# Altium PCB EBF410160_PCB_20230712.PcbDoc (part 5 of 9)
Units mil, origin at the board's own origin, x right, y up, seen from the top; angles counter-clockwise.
Board outline 5393.69 x 3858.26 mil, 6 copper layers (TOP, GND02, ART03, POW04, GND05, BOTTOM), stack 47.2 mil thick; 572 components, 434 nets, 2057 pads, 1177 vias.
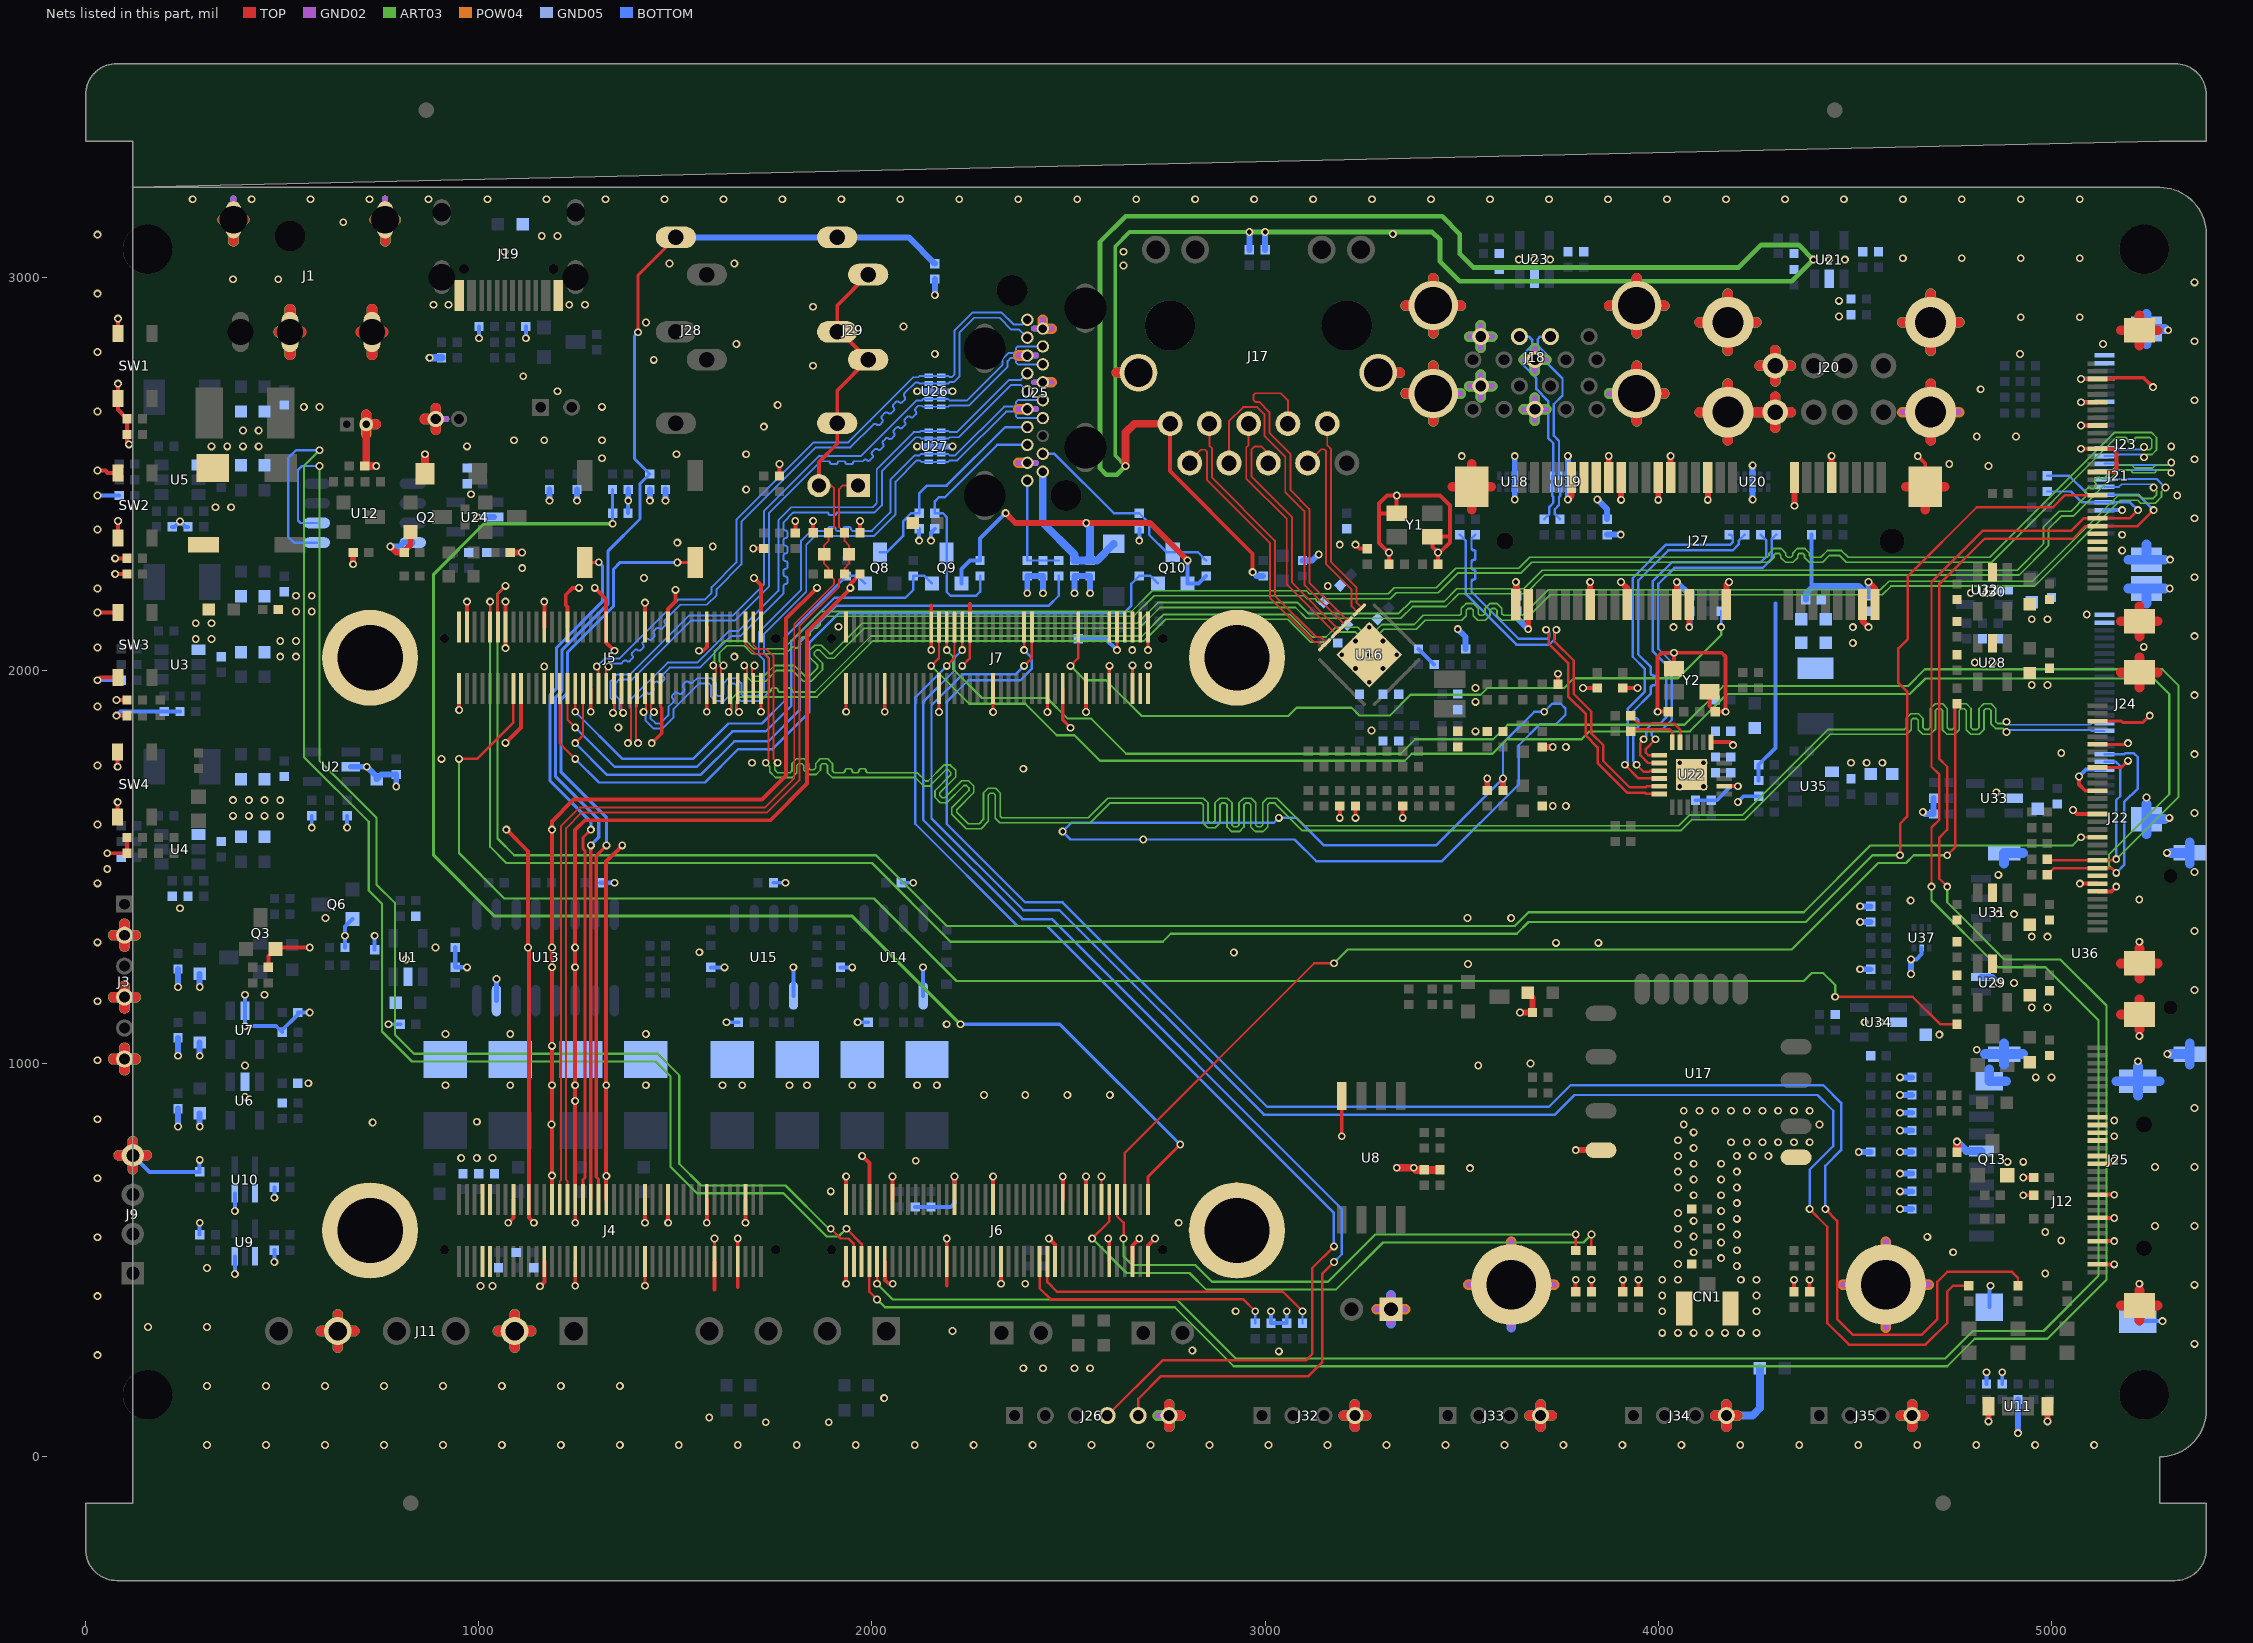
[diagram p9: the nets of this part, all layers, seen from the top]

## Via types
v1: diameter 20, hole 12, TOP to BOTTOM, 1177 vias

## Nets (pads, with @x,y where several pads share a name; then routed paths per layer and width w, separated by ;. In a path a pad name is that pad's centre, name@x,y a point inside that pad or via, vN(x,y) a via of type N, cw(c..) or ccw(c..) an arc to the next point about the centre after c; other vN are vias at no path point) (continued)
GND: (continued)
  other v1: 308.67,30 458.67,30 608.67,30 758.67,30 908.67,30 1058.67,30 1208.67,30 1358.67,30 1508.67,30 1658.67,30 1808.67,30 1958.67,30 2108.67,30 2258.67,30 2408.67,30 2558.67,30 2708.67,30 2858.67,30 3008.67,30 3158.67,30 3308.67,30 3458.67,30 3608.67,30 3758.67,30 3908.67,30 4058.67,30 4208.67,30 4358.67,30 4508.67,30 4658.67,30 4808.67,30 4958.67,30 5108.67,30 1730,87.75 1890,87.75 1586,99.75 2031,149 308.67,180 458.67,180 608.67,180 758.67,180 908.67,180 1058.67,180 1208.67,180 1358.67,180 2385,225 2435,225 2515,225 2555,225 30,258.34 3035,268 2815,270 5363.69,287.11 4010,315 4050,315 4090,315 4130,315 4170,315 4210,315 4250,315 2205,320 158.67,330 308.67,330 2925,370 4010,370 4250,370 30,408.34 4010,410 4250,410 1004,434 1035,434 5363.69,437.11 2390,440 5223.77,440 4010,450 4050,450 4210,450 4250,450 4984.39,465.78 308.67,480 4200,485 4050,490 4160,505 4090,520 4750,520 4200,525 4050,540 4160,545 5025,550 30,558.34 4684.49,559.16 4090,560 4200,565 4984.39,571.78 4050,580 4160,585 5263.69,587.11 5363.69,587.11 2780,595 4090,600 4200,605 4050,620 4160,625 4200,645 4090,665 4160,665 1895,675 4050,685 4200,685 4090,705 4160,705 30,708.34 4050,725 4200,725 3521,734 5263.69,737.11 5363.69,737.11 4090,745 4160,745 4888.52,750 4928.52,750 2111.42,752.79 955,760 995,760 1035,760 4050,765 4200,765 4240,765 4280,765 4090,785 4185,800 4225,800 4265,800 4305,800 4345,800 4385,800 4050,805 5160,815.16 4090,825 1185,845 4065,845 4410,845 730,850 995,852 5160,855.16 30,858.34 4065,880 4105,880 4145,880 4185,880 4225,880 4265,880 4305,880 4345,880 4385,880 5363.69,887.11 405,915 2284.8,920 2390,920 2496.96,920 2605,920 915,945 1080,945 1324,945 1424.93,945 1620,945 1670,945 1790,945 1835,945 1950,945 2000,945 2115,945 2165,945 566.48,950 4960,965 5000,965 405,995 3542,995 3675,1000 5220.05,1006 30,1008.34 5295,1024.09 4810,1035 5223.77,1070 4715,1073.5 915,1075 1080,1075 1424.93,1075 2190,1100 4525,1105 4565,1105 4950,1142.75 4990,1142.75 30,1158.34 455,1175 5363.69,1187.11 4905,1205 3516,1253 815,1265 1561,1283 2920.42,1282.58 890,1295 3740,1307 3847.54,1307 30,1308.34 5223.77,1309.99 4950,1322.75 4990,1322.75 5363.69,1337.11 610,1370 3515,1370 3625.89,1370 4865,1380 4905,1380 240,1395 4642,1415 5223.43,1417.4 30,1458.34 4865,1480 5363.69,1487.11 55,1495 5294,1535.9 30,1608.34 5300,1625 375,1630 415,1630 455,1630 495,1630 5363.69,1637.11 3731.8,1655.32 3765,1655 375,1670 415,1670 455,1670 495,1670 5241.84,1676.77 4860,1690 4055,1705 4115,1705 2385,1750 30,1758.34 1695,1765 4055,1765 4115,1765 4490,1765 4530,1765 4570,1765 905,1775 5363.69,1787.11 5025,1790 3765,1805 3535,1845 3270.46,1847 1355,1855 30,1908.34 3535,1920 5363.69,1937.11 3535,1955 4950,1962.75 4990,1962.75 3265,1970 3230,2005 3300,2005 1166.53,2010 2702.6,2012.87 4805,2020 4850,2020 495,2035 535,2035 1650,2035 3195,2040 3265,2040 3335,2040 2661.97,2051.61 30,2058.34 5235,2060 4495,2070 495,2075 535,2075 3230,2075 3300,2075 280,2080 320,2080 5363.69,2087.11 3265,2110 4495,2110 1915,2110.98 280,2120 320,2120 4950,2130 4990,2130 5090,2142.01 535,2150 575,2150 535,2190 575,2190 4795,2197 4835,2197 30,2208.34 5301,2208.31 3159.48,2214.48 1420,2235 5363.69,2237.11 1110.46,2260.07 5302,2281.7 5180,2305 1595,2315 3190,2320 1505,2325 5180,2345 30,2358.34 5363.69,2387.11 330,2415 370,2415 5320,2445 980,2448.2 1680,2460 4840,2520 4740,2525 5363.69,2537.11 1313.2,2539.68 3500,2545 1503,2550 1680,2550 320,2570 360,2570 400,2570 440,2570 970,2570 5305,2570 1089.74,2585.5 1166.59,2585.5 1313.27,2585.5 4810,2595 4910,2595 400,2610 440,2610 1725,2620 30,2658.34 555,2670 595,2670 1313.27,2670.37 1760,2675 5363.69,2687.11 1200,2710 4820,2715 1113,2748.38 1850,2775 1445,2790 2160,2805 4920,2805 30,2810 1655,2830 5130.99,2830 5363.69,2837.11 5297,2865.08 2080,2875 1425,2885 4922.1,2898.34 5072.1,2898.34 4460,2900 1850,2925 885,2930 923.12,2930 1230,2930 1270,2930 4460,2940 30,2958.34 5363.69,2987.11 375,2995 490,2995 2640,3030 1485,3035 1650,3035 3645,3045 3685,3045 3725,3045 4434.61,3044.76 4474.61,3044.76 4622.1,3048.34 4772.1,3048.34 4922.1,3048.34 5072.1,3048.34 1065,3065 2640,3065 1160,3105 1200,3105 30,3108.34 3325,3110 655,3140 272.1,3198.34 422.1,3198.34 572.1,3198.34 722.1,3198.34 872.1,3198.34 1022.1,3198.34 1172.1,3198.34 1322.1,3198.34 1472.1,3198.34 1622.1,3198.34 1772.1,3198.34 1922.1,3198.34 2072.09,3198.34 2222.09,3198.34 2372.09,3198.34 2522.09,3198.34 2672.09,3198.34 2822.09,3198.34 2972.09,3198.34 3122.09,3198.34 3272.09,3198.34 3422.09,3198.34 3572.09,3198.34 3722.09,3198.34 3872.09,3198.34 4022.09,3198.34 4172.1,3198.34 4322.1,3198.34 4472.1,3198.34 4622.1,3198.34 4772.1,3198.34 4922.1,3198.34 5072.1,3198.34
GPIO2_B7: J7.47 R48.2 | length 4494.6
  TOP w6.16: v1(2387.01,2051.61) J7.47@2387.01,2110.98 ; v1(4425,630) 4455,600 4455,350 4495,310 4670,310 4710,350 4710,445 4735,470 4900,470 4915,455 R48.2@4915,434.68
  BOTTOM w6.16: v1(2387.01,2051.61) 2406.09,2032.53 2406.09,2003.7 2377.38,1975 2245,1975 2190,1920 2190,1610 2390,1410 2485,1410 3005,890 3722,890 3777,945 4420,945 4465,900 4465,780 4425,740 v1(4425,630)
GPIO2_C0: J7.49 R49.2 | length 4390.6
  TOP w6.16: v1(2387.01,2011.61) 2406.69,2031.3 J7.49@2406.69,2110.98 ; v1(4385,630) 4430,585 4430,340 4485,285 4680,285 4735,340 4735,420 4749.68,434.68 R49.2@4790,434.68
  BOTTOM w6.16: v1(2387.01,2011.61) 2365.4,1990 2230,1990 2151.39,1911.39 2151.39,1623.61 2385,1390 2476.72,1390 2996.72,870 3737,870 3787,920 4405,920 4445,880 4445,790 4385,730 v1(4385,630)
HDMI_5V: C129.1 D32.1 D37.2 Q9.1 Q10.1 R157.1 R159.1 U25.18 | length 1343.1
  TOP w15: v1(2340,2400) 2365,2375 v1(2545,2375) 2707.5,2375 v1(2802.5,2280)
  BOTTOM w10: Q9.1@2227.5,2221 2227.5,2257.5 2249.68,2279.68 R157.1@2275,2279.68 2275,2335 v1(2340,2400) ; v1(2802.5,2280) Q10.1@2802.5,2221 2830.68,2221 R159.1@2850,2240.32
  BOTTOM w20: U25.18@2434.54,2505.36 2434.54,2375.46 2515,2295 D37.2@2515,2279.68 C129.1@2555,2279.68 ; v1(2545,2375) 2555,2365 C129.1@2555,2279.68 ; D32.1@2615,2321.93 2572.75,2279.68 C129.1@2555,2279.68
HDMI_TX0N_PORT: J5.48 U25.9 U27.4 U27.7 | length 1826.3
  TOP w4.88: J5.48@1402.75,1953.5 1402.75,1908.02 1399.72,1905 1399.72,1820.28 v1(1405,1815)
  BOTTOM w4.88: v1(1405,1815) 1399.35,1820.65 1399.35,1921.13 1420.42,1942.21 ; 1420.43,1942.21 cw(c1424.62,1938.01) 1428.82,1942.21 ccw(c1433.01,1946.4) 1437.21,1942.21 1442.62,1947.62 ccw(c1438.42,1951.82) 1442.62,1956.01 cw(c1446.82,1960.21) 1442.62,1964.4 1448.03,1969.82 cw(c1452.23,1965.62) 1456.42,1969.81 ccw(c1460.62,1974.01) 1464.81,1969.82 1470.23,1975.23 ccw(c1466.03,1979.42) 1470.23,1983.62 cw(c1474.42,1987.81) 1470.23,1992.01 1485.34,2007.12 1561.41,2007.12 1561.66,2007.36 1641.41,2087.12 1665.34,2087.12 1775,2196.78 1775,2214.41 cw(c1780,2214.41) 1780,2219.41 ccw(c1780,2224.41) 1785,2224.41 1785,2233.93 ccw(c1780,2233.93) 1780,2238.93 cw(c1780,2243.93) 1775,2243.93 1775,2253.45 cw(c1780,2253.45) 1780,2258.45 ccw(c1780,2263.45) 1785,2263.45 1785,2272.97 ccw(c1780,2272.97) 1780,2277.97 cw(c1780,2282.97) 1775,2282.97 1775,2292.49 cw(c1780,2292.49) 1780,2297.49 ccw(c1780,2302.49) 1785,2302.49 1785,2312.01 ccw(c1780,2312.01) 1780,2317.01 cw(c1780,2322.01) 1775,2322.01 1775,2331.53 cw(c1780,2331.53) 1780,2336.53 ccw(c1780,2341.53) 1785,2341.53 1785,2351.05 ccw(c1780,2351.05) 1780,2356.05 cw(c1780,2361.05) 1775,2361.05 1775,2376.78 1799.08,2400.87 cw(c1802.1,2397.85) 1802.1,2402.12 1886.02,2402.12 cw(c1886.02,2398.56) 1889.58,2398.56 ccw(c1893.14,2398.56) 1893.14,2395 1905.54,2395 ccw(c1905.54,2398.56) 1909.1,2398.56 cw(c1912.66,2398.56) 1912.66,2402.12 2007.12,2402.12 2025,2420 2025,2506.78 2111.3,2593.09 2121.91,2593.09 2125.31,2589.69 U27.4@2144.25,2589.69 U27.7@2175.75,2589.69 2194.06,2589.69 2197.46,2593.09 2221.3,2593.09 2354.48,2726.26 2378.88,2726.26 U25.9@2395.17,2709.97
HDMI_TX0P_PORT: J5.46 U25.7 U27.5 U27.6 | length 1769
  TOP w4.88: v1(1379,1815) 1386.85,1822.85 1386.85,1902.86 1383.06,1906.64 J5.46@1383.06,1953.5
  BOTTOM w4.88: v1(1379,1815) 1386.47,1822.47 1386.47,1926.47 1480,2020 1556.08,2020 1636.08,2100 1660,2100 1762.12,2202.12 1762.12,2382.12 1795,2415 2001.78,2415 2012.12,2425.34 2012.12,2512.12 2105.97,2605.97 2120.97,2605.97 2124.37,2609.37 U27.5@2144.25,2609.37 U27.6@2175.75,2609.37 2194.06,2609.37 2197.46,2605.97 2215.97,2605.97 2349.14,2739.14 2378.88,2739.14 U25.7@2395.17,2755.44
HDMI_TX1N_PORT: J5.44 U25.6 U26.1 U26.10 | length 1783.9
  TOP w4.88: J5.44@1363.38,1953.5 1363.38,1895.69 v1(1367.07,1892)
  BOTTOM w4.88: v1(1367.07,1892) 1357.88,1901.19 1357.88,1925 1347.88,1935 1347.88,1967.24 1357.76,1977.12 1390.34,1977.12 1540.34,2127.12 1652.12,2127.12 1737.88,2212.88 1737.88,2399.66 1870.34,2532.12 1889.76,2532.12 cw(c1889.76,2528.56) 1893.32,2528.56 ccw(c1896.88,2528.56) 1896.88,2525 1909.28,2525 ccw(c1909.28,2528.56) 1912.84,2528.56 cw(c1916.4,2528.56) 1916.4,2532.12 1928.8,2532.12 cw(c1928.8,2528.56) 1932.36,2528.56 ccw(c1935.92,2528.56) 1935.92,2525 1948.32,2525 ccw(c1948.32,2528.56) 1951.88,2528.56 cw(c1955.44,2528.56) 1955.44,2532.12 1977.12,2532.12 1980.19,2535.19 cw(c1983.26,2532.12) 1986.33,2535.19 1987.01,2534.51 ccw(c1990.76,2538.26) 1994.51,2534.51 2000.81,2540.81 ccw(c1997.06,2544.56) 2000.81,2548.31 cw(c2004.56,2552.06) 2000.81,2555.81 2007.12,2562.11 cw(c2010.87,2558.36) 2014.61,2562.11 ccw(c2018.37,2565.86) 2022.11,2562.12 2028.42,2568.42 ccw(c2024.67,2572.17) 2028.42,2575.92 cw(c2032.17,2579.67) 2028.42,2583.42 2034.72,2589.72 cw(c2038.47,2585.97) 2042.22,2589.72 ccw(c2045.97,2593.47) 2049.72,2589.72 2056.02,2596.02 ccw(c2052.27,2599.77) 2056.02,2603.52 cw(c2059.77,2607.27) 2056.02,2611.02 2062.33,2617.33 cw(c2066.08,2613.58) 2069.83,2617.33 ccw(c2073.58,2621.08) 2077.33,2617.33 2083.63,2623.63 ccw(c2079.88,2627.38) 2083.63,2631.13 cw(c2087.38,2634.88) 2083.63,2638.63 2089.93,2644.93 cw(c2093.68,2641.18) 2097.43,2644.93 ccw(c2101.18,2648.68) 2104.93,2644.93 2111.24,2651.24 ccw(c2107.49,2654.99) 2111.24,2658.74 cw(c2114.99,2662.49) 2111.24,2666.24 2118.22,2673.22 2126.78,2673.22 2129.37,2670.63 U26.1@2144.25,2670.63 U26.10@2175.75,2670.63 2194.06,2670.63 2197.46,2674.03 2247.25,2674.03 2345,2771.78 2345,2786.98 2352.76,2794.74 2361.3,2794.74 2366.18,2789.86 2366.18,2783.31 2371.06,2778.43 U25.6@2434.54,2778.43
HDMI_TX1P_PORT: J5.42 U25.4 U26.2 U26.9 | length 1726.1
  TOP w4.88: v1(1341.07,1892) 1343.69,1894.62 J5.42@1343.69,1953.5
  BOTTOM w4.88: v1(1341.07,1892) 1345,1895.93 1345,1919.66 1335,1929.66 1335,1972.58 1352.42,1990 1385,1990 1535,2140 1646.79,2140 1725,2218.22 1725,2405 1865,2545 1971.78,2545 2112.89,2686.1 2126.1,2686.1 2130.31,2690.31 U26.2@2144.25,2690.31 U26.9@2175.75,2690.31 2194.06,2690.31 2197.46,2686.91 2241.91,2686.91 2332.12,2777.12 2332.12,2792.32 2347.42,2807.62 2361.3,2807.62 2366.18,2812.5 2366.18,2819.06 2371.06,2823.94 U25.4@2434.54,2823.94
HDMI_TX2N_PORT: J5.40 U25.3 U26.4 U26.7 | length 1742.5
  TOP w4.88: J5.40@1324.01,1953.5 1324.01,2004.01 v1(1330,2010)
  BOTTOM w4.88: v1(1330,2010) 1337.12,2017.12 1362.12,2017.12 1369.11,2024.11 cw(c1372.86,2020.36) 1376.61,2024.11 ccw(c1380.36,2027.86) 1384.11,2024.11 1390.41,2030.41 ccw(c1386.66,2034.16) 1390.41,2037.91 cw(c1394.16,2041.66) 1390.41,2045.41 1396.72,2051.72 cw(c1400.47,2047.97) 1404.22,2051.72 ccw(c1407.96,2055.46) 1411.71,2051.71 1418.02,2058.02 ccw(c1414.27,2061.77) 1418.02,2065.52 cw(c1421.77,2069.27) 1418.02,2073.02 1424.32,2079.32 cw(c1428.07,2075.57) 1431.82,2079.32 ccw(c1435.57,2083.07) 1439.32,2079.32 1445.62,2085.62 ; 1445.62,2093.12 cw(c1449.37,2096.87) 1445.62,2100.62 1451.93,2106.93 cw(c1455.68,2103.18) 1459.43,2106.93 ccw(c1463.18,2110.68) 1466.93,2106.93 1473.23,2113.23 ccw(c1469.48,2116.98) 1473.23,2120.73 cw(c1476.98,2124.48) 1473.23,2128.23 1512.12,2167.12 1580.34,2167.12 1605,2191.78 1605,2206.78 1667.88,2269.66 1667.88,2377.88 1857.12,2567.12 1945.12,2567.12 2003.49,2625.49 cw(c2007.74,2621.24) 2011.99,2625.49 ccw(c2016.24,2629.74) 2020.49,2625.49 2025.79,2630.79 ccw(c2021.54,2635.04) 2025.79,2639.29 cw(c2030.04,2643.54) 2025.79,2647.79 2032.78,2654.78 cw(c2037.03,2650.53) 2041.28,2654.78 ccw(c2045.53,2659.03) 2049.78,2654.78 2055.08,2660.08 ccw(c2050.83,2664.33) 2055.08,2668.58 cw(c2059.33,2672.83) 2055.08,2677.08 2060.39,2682.39 cw(c2064.64,2678.14) 2068.89,2682.39 ccw(c2073.14,2686.63) 2077.39,2682.38 2082.69,2687.69 ccw(c2078.44,2691.94) 2082.69,2696.19 cw(c2086.94,2700.44) 2082.69,2704.69 2110.86,2732.86 2117.76,2732.86 2120.94,2729.69 U26.4@2144.25,2729.69 U26.7@2175.75,2729.69 2194.06,2729.69 2197.46,2733.09 2208.09,2733.09 2222.88,2747.88 2222.88,2859.66 2260.34,2897.12 2324.66,2897.12 2354.66,2867.12 2374.43,2867.12 U25.3@2395.17,2846.38 ; 1445.63,2085.62 ccw(c1441.88,2089.37) 1445.63,2093.12
HDMI_TX2P_PORT: J5.38 U25.1 U26.5 U26.6 | length 1684.1
  TOP w4.88: v1(1300,2010) 1304.32,2005.68 J5.38@1304.32,1953.5
  BOTTOM w4.88: v1(1300,2010) 1320,2030 1356.79,2030 1506.79,2180 1575,2180 1592.12,2197.12 1592.12,2212.12 1655,2275 1655,2383.22 1851.78,2580 1939.78,2580 1994.38,2634.6 cw(c2007.8,2621.3) 1994.5,2634.71 2105.53,2745.74 2117.31,2745.74 2120.94,2749.37 U26.5@2144.25,2749.37 U26.6@2175.75,2749.37 2194.06,2749.37 2197.46,2745.97 2202.75,2745.97 2210,2753.22 2210,2865 2255,2910 2330,2910 2360,2880 2383.32,2880 U25.1@2395.17,2891.85
HDMI_TX_CEC_PORT: D36.2 Q8.3 U25.13 | length 558
  BOTTOM w6.16: Q8.3@2020,2301 2038,2301 2080,2343 2080,2380 2099.68,2399.68 D36.2@2120,2399.68 2120,2450 2140,2470 2190,2470 2339.02,2619.02 U25.13@2395.17,2619.02
HDMI_TX_HPD_PORT: D33.2 R153.2 R154.1 U25.19 | length 283
  BOTTOM w6.16: U25.19@2395.17,2482.61 2395,2482.44 D33.2@2395,2279.68 R154.1@2435,2279.68 R153.2@2475,2279.68
HDMI_TX_HPDIN: J5.34 R153.1 | length 1748.8
  TOP w6.16: v1(1245.27,1815) 1264.95,1834.68 J5.34@1264.95,1953.5
  BOTTOM w6.16: v1(1245.27,1815) 1325.13,1735.14 1565.14,1735.14 1650,1820 1736.71,1820 1815.86,1899.14 1815.86,2070.86 1910,2165 2450,2165 2475,2190 R153.1@2475,2240.32
HDMI_TXCLKN_PORT: J5.50 U25.12 U27.1 U27.10 | length 1812.3
  TOP w4.88: v1(1419.28,1894.43) 1425.38,1900.53 1425.38,1913.62 1422.43,1916.57 J5.50@1422.43,1953.5
  BOTTOM w4.88: v1(1419.28,1894.43) 1423.43,1890.28 1423.43,1873.23 1444.54,1852.12 1467.12,1852.12 1495,1880 1495,1901.78 1560.34,1967.12 1585.24,1967.12 1590.12,1962.24 1590.12,1934.54 1602.55,1922.12 1622.98,1922.12 1635.4,1934.54 1635.4,1962.24 1640.28,1967.12 1650.04,1967.12 1654.92,1962.24 1654.92,1934.54 1667.35,1922.12 1715.34,1922.12 1737.88,1944.66 1737.88,2032.12 1725,2045 1725,2091.78 1832.88,2199.66 1832.88,2319.66 1855.34,2342.12 2005.34,2342.12 2060,2396.78 2060,2480 2114.03,2534.03 2121.91,2534.03 2125.31,2530.63 U27.1@2144.25,2530.63 U27.10@2175.75,2530.63 2194.06,2530.63 2197.46,2534.03 2217.25,2534.03 2341.43,2658.21 2361.3,2658.21 2366.18,2653.33 2366.18,2646.78 2371.06,2641.9 U25.12@2434.54,2641.9
HDMI_TXCLKP_PORT: J5.52 U25.10 U27.2 U27.9 | length 1851.8
  TOP w4.88: J5.52@1442.12,1953.5 1442.12,1917.12 1438.26,1913.26 1438.26,1901.46 v1(1445.28,1894.43)
  BOTTOM w4.88: v1(1445.28,1894.43) 1436.31,1885.47 1436.31,1878.57 1449.88,1865 1461.78,1865 1482.12,1885.34 1482.12,1907.12 1493.28,1918.28 ccw(c1488.28,1923.28) 1493.28,1928.28 cw(c1498.28,1933.28) 1493.28,1938.28 1497.08,1942.08 cw(c1502.08,1937.08) 1507.08,1942.08 ccw(c1512.08,1947.08) 1517.08,1942.08 1520.89,1945.89 ccw(c1515.89,1950.89) 1520.89,1955.89 cw(c1525.89,1960.89) 1520.89,1965.89 1524.69,1969.69 cw(c1529.69,1964.69) 1534.69,1969.69 ccw(c1539.69,1974.69) 1544.69,1969.69 1555,1980 1590.58,1980 1603,1967.58 1603,1939.88 1607.88,1935 1617.64,1935 1622.52,1939.88 1622.52,1967.58 1634.95,1980 1655.38,1980 1667.8,1967.58 1667.8,1939.88 1672.68,1935 1710,1935 1725,1950 1725,2026.78 1712.12,2039.66 1712.12,2097.12 1820,2205 1820,2330 1845,2355 1883.1,2355 ccw(c1883.1,2360) 1888.1,2360 cw(c1893.1,2360) 1893.1,2365 1902.62,2365 cw(c1902.62,2360) 1907.62,2360 ccw(c1912.62,2360) 1912.62,2355 1922.14,2355 ccw(c1922.14,2360) 1927.14,2360 cw(c1932.14,2360) 1932.14,2365 1941.66,2365 cw(c1941.66,2360) 1946.66,2360 ccw(c1951.66,2360) 1951.66,2355 2000,2355 2047.12,2402.12 2047.12,2485.34 2108.69,2546.91 2120.97,2546.91 2124.37,2550.31 U27.2@2144.25,2550.31 U27.9@2175.75,2550.31 2194.06,2550.31 2197.46,2546.91 2211.91,2546.91 2336.09,2671.09 2361.3,2671.09 2366.18,2675.97 2366.18,2682.53 2371.06,2687.41 U25.10@2434.54,2687.41
HDMI_TXDDC_SCL_PORT: D35.2 Q9.3 R157.2 U25.15 | length 682.5
  BOTTOM w6.16: R157.2@2275,2240.32 2275,2200 2265,2190 2200.08,2190 2190,2200.08 Q9.3@2190,2301 2190,2390 2180.32,2399.68 D35.2@2160,2399.68 2160,2430 2170,2440 2185,2440 2318.54,2573.54 U25.15@2395.17,2573.54
HDMI_TXDDC_SDA_PORT: D34.2 Q10.3 R159.2 U25.16 | length 545.2
  BOTTOM w6.16: U25.16@2434.54,2550.87 2464.13,2550.87 2615.32,2399.68 D34.2@2680,2399.68 2705,2374.68 2705,2345 2749,2301 Q10.3@2765,2301 2828.68,2301 R159.2@2850,2279.68
HDMITX_CEC_M0: J5.32 Q8.2 R155.2 | length 1140.1
  TOP w6.16: v1(1245.27,1895) J5.32@1245.27,1953.5
  BOTTOM w6.16: v1(1245.27,1895) 1365.27,1775 1545,1775 1635,1865 1720,1865 1778,1923 1778,2083.32 R155.2@1935,2240.32 1963.18,2240.32 Q8.2@1982.5,2221
HDMITX_SCL: J5.30 Q9.2 R156.2 | length 1381.7
  TOP w6.16: J5.30@1225.58,1953.5 1225.58,1874.68 v1(1245.27,1855)
  BOTTOM w6.16: v1(1245.27,1855) 1345.27,1755 1555,1755 1645,1845 1730,1845 1795,1910 1795,2075 1905,2185 2085,2185 2105,2205 R156.2@2105,2240.32 2133.18,2240.32 Q9.2@2152.5,2221
HDMITX_SDA: J5.28 Q10.2 R158.2 | length 2063.6
  TOP w6.16: J5.28@1205.9,1953.5 1205.9,1814.37 v1(1245.27,1775)
  BOTTOM w6.16: v1(1245.27,1775) 1305.27,1715 1575,1715 1660,1800 1746.98,1800 1840.99,1894.01 1840.99,2070.99 1915,2145 2640,2145 2660,2165 2660,2220.32 R158.2@2680,2240.32 2708.18,2240.32 Q10.2@2727.5,2221
HOST1_DM: J18.2 R136.1 U19.4 U19.7 | length 545.8
  BOTTOM w6.23: J18.2@3725.66,2849.17 3699.64,2849.17 3693.41,2842.94 3693.41,2826.51 3717.05,2802.87 3717.05,2782.18 3756.43,2742.8 3756.43,2699.06 3734.25,2676.88 3734.25,2597.14 3747.59,2583.8 3747.59,2498.47 U19.7@3750.31,2495.75 U19.4@3750.31,2464.25 3750.31,2443.63 3747.59,2440.91 3747.59,2420.47 3737.11,2410 3737.11,2397.57 R136.1@3750,2384.68
HOST1_DP: J18.3 R137.1 U19.5 U19.6 | length 545.8
  BOTTOM w6.23: J18.3@3646.92,2849.17 3670.83,2849.17 3679.18,2840.82 3679.18,2826.53 3655.51,2802.87 3655.51,2777.37 3690,2742.88 3690,2715.34 3720.02,2685.32 3720.02,2591.24 3733.36,2577.91 3733.36,2498.47 U19.6@3730.63,2495.75 U19.5@3730.63,2464.25 3730.63,2443.63 3733.36,2440.91 3733.36,2426.37 3722.89,2415.89 3722.89,2397.57 R137.1@3710,2384.68
HP_DET: C173.1 J6.80 R215.1 | length 3688.2
  TOP w8: J6.80@2701.97,654.29 2701.97,711.97 v1(2784,794)
  ART03 w8: v1(1340.32,2373.2) 1013.2,2373.2 885,2245 885,1530 1040,1375 1950,1375 v1(2225,1100)
  BOTTOM w8: R215.1@1340,2460.32 1340,2400.32 C173.1@1340.32,2400 v1(1340.32,2373.2) ; v1(2225,1100) 2478,1100 v1(2784,794)
HP_SNS: J4.36 J28.1 J29.1 R216.1 R218.1 | length 3346.4
  TOP w8: J4.36@1284.64,654.29 1284.64,1554.68 v1(1284.95,1555) ; v1(1405,2860) 1405,3005.01 J28.1@1501.39,3101.41
  BOTTOM w8: v1(1284.95,1555) 1284.95,1555.32 1305,1575.36 1305,1620 1195.27,1729.73 1195.27,1932.01 1211.91,1948.65 1211.91,2052.61 1329,2169.7 1329,2304 1410,2385 1410,2474.68 R216.1@1435,2499.68 1396,2538.68 1396,2851 v1(1405,2860)
  BOTTOM w15: J28.1@1501.39,3101.41 J29.1@1911.61,3101.41 2093.28,3101.41 R218.1@2160,3034.68
HPL_OUT: C175.1 J4.34 | length 1770.8
  TOP w8: J4.34@1264.95,654.29 1264.95,704.95 1270,710 1270,1541.67 1264.95,1546.71 1264.95,1574.95 v1(1285,1595) ; C175.1@1270,2274.76 1304.76,2274.76 v1(1305,2275)
  BOTTOM w8: v1(1285,1595) 1285,1615 1181.27,1718.73 1181.27,1937.81 1197.91,1954.45 1197.91,2058.41 1315,2175.5 1315,2265 v1(1305,2275)
HPR_OUT: C176.1 J4.38 | length 1934.3
  TOP w8: J4.38@1304.32,654.29 1304.32,705.68 1298.64,711.36 1298.64,1528.64 v1(1325,1555) ; v1(1505,2274.76) C176.1@1550,2274.76
  BOTTOM w8: v1(1325,1555) 1325,1625 1209.27,1740.73 1209.27,1926.21 1225.91,1942.85 1225.91,2046.81 1343,2163.9 1343,2258 1359.76,2274.76 v1(1505,2274.76)
HUB_3V3: C126.1 C127.1 C128.1 R144.1 R145.1 R151.2 U22.1 U22.20 | length 215.8
  TOP w10: U22.1@4134.21,1817.68 4182.32,1817.68 v1(4190,1810) ; U22.20@4167.68,1705.47 v1(4202.37,1705.47)
  BOTTOM w10: R144.1@4095,1669.68 R145.1@4135,1669.68 4149.68,1669.68 4185.47,1705.47 v1(4202.37,1705.47)
HUB_DM1: R129.2 U22.11 | length 1026.6
  TOP w6.23: v1(3740.89,2103.29) 3735.2,2097.61 3735.2,2074.8 3785,2025 3785,1940 3830,1895 3830,1840 3860,1810 3860,1770 3927.26,1702.74 3967.74,1702.74 3970.47,1705.47 U22.11@4002.32,1705.47
  BOTTOM w6.23: R129.2@3495,2345.32 3510.77,2329.55 3510.77,2194.11 3639.11,2065.77 3722.8,2065.77 3737.37,2080.34 3737.37,2099.78 v1(3740.89,2103.29)
HUB_DM2: R138.2 U22.9 | length 926
  TOP w6.23: v1(3945,1760) 3963.16,1741.84 3976.84,1741.84 3979.84,1744.84 U22.9@4002.32,1744.84
  BOTTOM w6.23: v1(3945,1760) 3936.23,1768.77 3936.23,1846.31 cw(c3943.11,1846.31) 3943.11,1853.19 ccw(c3943.11,1859.42) 3949.34,1859.42 3949.34,1871.88 ccw(c3943.11,1871.88) 3943.11,1878.11 cw(c3943.11,1885) 3936.23,1885 3936.23,1896.23 3980.38,1940.38 3980.38,1954.72 cw(c3987.69,1954.72) 3987.69,1962.03 ccw(c3987.69,1969.35) 3995,1969.35 3995,1979.64 ccw(c3987.69,1979.64) 3987.69,1986.95 cw(c3987.69,1994.27) 3980.38,1994.27 3980.38,2009.62 3949.23,2040.77 3949.23,2229.11 4025.89,2305.77 4189.66,2305.77 4204.23,2320.34 4204.23,2329.55 R138.2@4220,2345.32
HUB_DM3: R131.2 U22.7 | length 908.4
  TOP w6.23: v1(3992.8,1825) 3968.4,1800.59 3968.4,1790.44 3974.63,1784.21 U22.7@4002.32,1784.21
  BOTTOM w6.23: v1(3992.8,1825) 3983.31,1834.5 3983.31,1843.31 3990,1850 4010,1850 4034.23,1874.23 4034.23,2020.89 4000,2055.12 4000,2219.88 4040.89,2260.77 4265.77,2260.77 4289.23,2284.23 4289.23,2334.55 R131.2@4300,2345.32
HUB_DM4: R210.2 U22.5 | length 172.3
  TOP w6.23: R210.2@3929.68,1885 3949.68,1865 4040,1865 4055.47,1849.53 U22.5@4055.47,1817.68
HUB_DP1: R130.2 U22.12 | length 1025.6
  TOP w6.23: v1(3714.89,2103.29) 3720.97,2097.21 3720.97,2068.9 3770.77,2019.11 3770.77,1934.11 3815.77,1889.11 3815.77,1834.11 3845.77,1804.11 3845.77,1764.11 3921.36,1688.52 3966.49,1688.52 3969.21,1685.79 U22.12@4002.32,1685.79
  BOTTOM w6.23: R130.2@3535,2345.32 3525,2335.32 3525,2310.94 ccw(c3530,2310.94) 3530,2305.94 cw(c3530,2300.94) 3535,2300.94 3535,2286.02 cw(c3530,2286.02) 3530,2281.02 ccw(c3530,2276.02) 3525,2276.02 3525,2261.1 ccw(c3530,2261.1) 3530,2256.1 cw(c3530,2251.1) 3535,2251.1 3535,2236.18 cw(c3530,2236.18) 3530,2231.18 ccw(c3530,2226.18) 3525,2226.18 3525,2200 3645,2080 3716.91,2080 3723.14,2086.23 3723.14,2095.04 v1(3714.89,2103.29)
HUB_DP2: R139.2 U22.10 | length 929.1
  TOP w6.23: v1(3915,1760) 3949.84,1725.16 U22.10@4002.32,1725.16
  BOTTOM w6.23: v1(3915,1760) 3922,1767 3922,1902.12 3966.15,1946.27 3966.15,2003.73 3935,2034.88 3935,2235 4020,2320 4183.77,2320 4190,2326.23 4190,2339.09 4183.77,2345.32 R139.2@4180,2345.32
HUB_DP3: R132.2 U22.8 | length 928.1
  TOP w6.23: v1(3962.8,1825) 3954.17,1816.36 3954.17,1784.54 3974.18,1764.53 U22.8@4002.32,1764.53
  BOTTOM w6.23: v1(3962.8,1825) 3969.08,1831.27 3969.08,1849.2 3984.11,1864.23 4004.11,1864.23 4020,1880.12 4020,2015 3985.77,2049.23 3985.77,2225.77 4035,2275 4259.87,2275 4275,2290.13 4275,2330.32 R132.2@4260,2345.32
HUB_DP4: R211.2 U22.6 | length 136.9
  TOP w6.23: R211.2@3929.68,1845 3934.68,1850 4029.56,1850 4035.79,1843.77 U22.6@4035.79,1817.68
I2C0_SCL_PMIC: J6.3 U12.6 | length 3328.3
  TOP w6.16: v1(1895,580) 1920,555 1940,555 1953.94,541.06 J6.3@1953.94,496.81
  ART03 w5.61: v1(595,2520) 595,1770 740,1625 740,1455 787.12,1407.88 787.12,1072.88 835,1025 1455,1025 1510,970 1510,745 1565,690 1780,690 1890,580 v1(1895,580)
  BOTTOM w6.16: U12.6@587.95,2375 546.16,2375 540,2381.16 540,2510 550,2520 v1(595,2520)
I2C0_SDA_PMIC: J6.5 U12.5 | length 3584.5
  TOP w6.16: v1(1935,580) 1973.62,541.38 J6.5@1973.62,496.81
  ART03 w5.61: v1(595,2560) 555,2520 555,1780 720,1615 720,1440 753.51,1406.48 753.51,1081.48 830,1005 1450,1005 1487.5,967.5 1487.5,737.5 1555,670 1775,670 1885,560 1915,560 v1(1935,580)
  BOTTOM w6.16: U12.5@587.95,2325 530,2325 515,2340 515,2540 535,2560 v1(595,2560)
I2C1_SCL: J6.7 J21.9 J23.6 R163.2 | length 6368.9
  TOP w6.16: J6.7@1993.31,496.81 1993.31,419.69 v1(2012.99,400) ; v1(4735,1450) 4715,1470 4715,1575 4735,1595 4735,1755 4715,1775 4715,2220 4830,2335 5055,2335 5087.05,2367.05 J21.9@5117.47,2367.05 5219.37,2367.05 v1(5260,2407.68)
  ART03 w5.61: v1(2012.99,400) 2032.99,380 2770,380 2920,230 4735,230 4805,300 4990,300 5140,450 5140,1147.67 5022.83,1264.84 4880.16,1264.84 4735,1410 v1(4735,1450)
  BOTTOM w6.16: R163.2@4989.68,2495 5045,2495 5092.95,2447.05 J23.6@5135.46,2447.05 5220.63,2447.05 v1(5260,2407.68)
I2C1_SDA: J6.9 J21.10 J23.5 R167.2 | length 6208
  TOP w6.16: v1(2012.99,440) J6.9@2012.99,496.81 ; v1(4695,1450) 4695,1600 4715,1620 4715,1735 4695,1755 4695,2225 4825,2355 5050,2355 5081.74,2386.74 J21.10@5117.47,2386.74 5199.06,2386.74 v1(5220,2407.68)
  ART03 w5.61: v1(2012.99,440) 2052.99,400 2775,400 2925,250 4730,250 4800,320 4980,320 5120,460 5120,1110 4985,1245 4865,1245 4695,1415 v1(4695,1450)
  BOTTOM w6.16: R167.2@4989.68,2455 5050,2455 5077.64,2427.36 J23.5@5135.46,2427.36 5200.31,2427.36 v1(5220,2407.68)
I2C2_SCL_M1: J6.51 R222.2 | length 671.4
  TOP w6.16: J6.51@2426.38,496.81 2426.38,428.62 2455,400 2945,400 v1(2975,370)
  BOTTOM w6.16: R222.2@2975,339.68 v1(2975,370)
I2C2_SDA_M1: J6.53 R221.2 | length 762.8
  TOP w6.16: J6.53@2446.06,496.81 2446.06,443.94 2470,420 3045,420 v1(3095,370)
  BOTTOM w6.16: R221.2@3095,339.68 v1(3095,370)
I2C3_SCL_M0: J6.72 R219.2 | length 1418.2
  TOP w6.16: J6.72@2623.23,654.29 2623.23,611.77 2640,595 v1(2640,555) ; R219.2@3790,524.68 v1(3790,565)
  ART03 w5.61: v1(2640,555) 2640,510 2662.5,487.5 2822.5,487.5 2865,445 3160,445 3280,565 v1(3790,565)
I2C3_SDA_M0: J6.70 R220.2 | length 1539.5
  TOP w6.16: v1(2560,555) 2603.54,598.54 J6.70@2603.54,654.29 ; R220.2@3830,524.68 v1(3830,565)
  ART03 w5.61: v1(2560,555) 2647.5,467.5 2807.5,467.5 2850,425 3180,425 3300,545 3810,545 v1(3830,565)
I2C4_SCL_M0: J7.29 J26.4 | length 2985.5
  TOP w6.16: v1(2190.16,2011.61) 2209.84,2031.3 J7.29@2209.84,2110.98 ; J26.4@2598.42,104.49 2738.93,245 3103.84,245 3120,261.16 3120,480 v1(3175,535)
  BOTTOM w6.16: v1(2190.16,2011.61) 2110,1931.45 2110,1610 2370.01,1349.99 2445.01,1349.99 3175,620 v1(3175,535)
I2C4_SDA_M0: J7.31 J26.5 | length 2967
  TOP w6.16: v1(2229.53,2051.61) J7.31@2229.53,2110.98 ; J26.5@2677.16,104.49 2677.16,147.16 2735,205 3110,205 3145,240 3145,465 v1(3175,495)
  BOTTOM w6.16: v1(2229.53,2051.61) 2209.24,2031.32 2209.24,1999.24 2130,1920 2130,1620 2382.5,1367.5 2457.5,1367.5 3195,630 3195,515 v1(3175,495)
I2C5_SCL_M0: J7.25 J22.9 J24.6 R165.2 | length 4580.3
  TOP w6.16: v1(2150.79,2011.61) 2170.47,2031.3 J7.25@2170.47,2110.98 ; R165.2@4989.68,1480 5006.73,1497.05 J22.9@5117.47,1497.05 5152.95,1497.05 v1(5165,1485)
  ART03 w5.61: v1(2150.79,2011.61) 2247.39,1915.01 2389.99,1915.01 2470,1835 2515,1835 2580,1770 3355,1770 3373.2,1788.19 3578.2,1788.19 3615,1825 3805,1825 3825,1845 4080,1845 4175,1940 4640,1940 4679.56,1979.56 5260.44,1979.56 5300,1940 5300,1685 5146.19,1531.19 5146.19,1503.81 v1(5165,1485)
  BOTTOM w6.16: J24.6@5135.46,1787.05 5185.06,1787.05 5187.1,1789.08 5210,1789.08 5220,1779.08 5220,1700 5185,1665 5185,1505 v1(5165,1485)
I2C5_SDA_M0: J7.27 J22.10 J24.5 R169.2 | length 4396.7
  TOP w6.16: v1(2190.16,2051.61) J7.27@2190.16,2110.98 ; R169.2@4989.68,1520 4992.94,1516.74 J22.10@5117.47,1516.74 5161.74,1516.74 v1(5165,1520)
  ART03 w5.61: v1(2190.16,2051.61) 2206.96,2034.81 2206.96,2003.04 2280,1930 2445,1930 2497.68,1877.33 2557.68,1877.33 2646.8,1788.19 3345,1788.19 3381.8,1825 3580,1825 3616.8,1861.81 4066.8,1861.81 4165,1960 4635,1960 4678.2,2003.19 5281.81,2003.19 5323.64,1961.36 5323.64,1678.64 v1(5165,1520)
  BOTTOM w6.16: J24.5@5135.46,1767.36 5164.14,1767.36 5175,1756.51 5175,1680 5165,1670 v1(5165,1520)
LCD0_BL_PWM: J5.9 J21.13 | length 5769.4
  TOP w6.16: J5.9@1028.73,2110.98 v1(1028.73,2175) ; v1(4615,1530) 4615,1610 4633.08,1628.08 4633.08,1945.92 4610.92,1968.08 4610.92,2055.92 4635,2080 4635,2240 4810,2415 5004.21,2415 5035,2445.79 J21.13@5117.47,2445.79
  ART03 w5.61: v1(1028.73,2175) 1028.73,1551.27 1070,1510 2000,1510 2200,1310 2740,1310 2760,1330 3640,1330 3670,1360 4375,1360 4545,1530 v1(4615,1530)
LCD1_BL_PWM: J5.11 J22.13 | length 5018.8
  TOP w6.16: J5.11@1048.42,2110.98 1048.42,2195.32 v1(1068.1,2215) ; v1(5075,1575.79) J22.13@5117.47,1575.79
  ART03 w5.61: v1(1068.1,2215) 1047.54,2194.43 1047.54,1572.46 1090,1530 2010,1530 2190,1350 3635,1350 3670,1385 4370,1385 4540,1555 5054.21,1555 v1(5075,1575.79)
MDIN0_PHY: J17.3 U16.2 | length 505.5
  TOP w4.88: J17.3@3108.13,2527.52 3143.22,2562.61 3150.12,2562.61 3155,2557.73 3155,2270 3220,2205 3220,2162.95 U16.2@3234.37,2148.57
MDIN1_PHY: J17.7 U16.5 | length 839.6
  TOP w4.88: J17.7@2908.13,2527.52 2908.13,2634 2944.13,2670 2980,2670 2998.07,2651.93 2998.07,2596.93 3051.23,2543.77 3051.23,2453.77 3100,2405 3100,2218.16 3200.97,2117.19 U16.5@3200.97,2115.16
MDIN2_PHY: J17.6 U16.7 | length 631
  TOP w4.88: J17.6@2958.13,2627.52 2958.13,2573.13 2952.12,2567.12 2952.12,2488.1 3055,2385.22 3055,2218.63 3178.7,2094.93 U16.7@3178.7,2092.9
MDIN3_PHY: J17.9 U16.10 | length 688.8
  TOP w4.88: J17.9@2808.13,2527.52 2808.13,2533.13 2836.35,2561.35 2847.24,2561.35 2852.12,2556.47 2852.12,2484.66 3012.12,2324.66 3012.12,2184.66 3124.66,2072.12 3136.72,2072.12 3145.29,2063.55 U16.10@3145.29,2059.49
MDIP0_PHY: J17.2 U16.1 | length 504
  TOP w4.88: J17.2@3158.13,2627.52 3158.13,2572.81 3167.88,2563.06 3167.88,2275.34 3232.88,2210.34 3232.88,2172.34 U16.1@3245.51,2159.71
MDIP1_PHY: J17.4 U16.4 | length 838.4
  TOP w4.88: J17.4@3058.13,2627.52 3058.13,2686.87 3040,2705 2974.88,2705 2970,2700.12 2970,2687.88 2975,2682.88 2985.34,2682.88 3010.95,2657.27 3010.95,2604.05 3064.11,2550.89 3064.11,2459.11 3112.88,2410.34 3112.88,2223.49 3210.07,2126.3 U16.4@3212.1,2126.3
MDIP2_PHY: J17.5 U16.6 | length 630.5
  TOP w4.88: J17.5@3008.13,2527.52 3008.13,2551.87 2990,2570 2973.22,2570 2965,2561.78 2965,2493.44 3067.88,2390.56 3067.88,2223.96 3187.81,2104.03 U16.6@3189.84,2104.03
MDIP3_PHY: J17.8 U16.9 | length 687.5
  TOP w4.88: J17.8@2858.13,2627.52 2858.13,2571.87 2865,2565 2865,2490 3025,2330 3025,2190 3130,2085 3142.05,2085 U16.9@3156.43,2070.63
MIC_INN: C174.2 D44.2 J4.30 J30.1 R217.1 | length 2445.4
  TOP w4.88: J4.30@1225.58,654.29 1225.58,701.15 1222.18,704.55 1222.18,1598.96 1261.9,1638.68 1733.68,1638.68 1815.24,1720.24 1815.24,2112.02 1916.44,2213.22 1916.44,2231.12 R217.1@1930.32,2245 1930.32,2260.32 1941.5,2271.5 C174.2@1941.5,2295 1941.5,2318.19 1930.32,2329.37 D44.2@1930.32,2350 1916.44,2363.88 1916.44,2461.44 1925,2470 J30.1@1965,2470
MIC_INP: C174.1 D41.2 J4.28 J29.2 J29.3 J29.4 J29.5 J30.2 R213.2 | length 3095.2
  TOP w4.88: J4.28@1205.9,654.29 1205.9,701.15 1209.3,704.55 1209.3,1604.3 1256.56,1651.56 1728.34,1651.56 1802.36,1725.58 1802.36,2117.36 1903.56,2218.56 1903.56,2231.12 R213.2@1889.68,2245 1889.68,2260.32 1878.5,2271.5 C174.1@1878.5,2295 1878.5,2318.19 1889.68,2329.37 D41.2@1889.68,2350 1903.56,2363.88 1903.56,2463.41 1896.97,2470 J30.2@1865,2470
  TOP w10: J30.2@1865,2470 1865,2530 1911.61,2576.61 J29.4@1911.61,2628.96 1911.61,2711.64 J29.3@1990.35,2790.38 1919.49,2861.24 J29.5@1911.61,2861.24 1911.61,2928.17 J29.2@1990.35,3006.91
MINIPCIE_3V3: C155.1 C159.1 C160.1 C161.1 C167.1 C168.1 C169.1 C170.1 J27.2 J27.24 J27.39 J27.41 J27.52 L10.2 R201.1 R205.1 | length 1145.4
  TOP w15: J27.52@3637.85,2168.04 v1(3637.85,2225) ; v1(4078.79,2110) J27.24@4078.79,2168.04 ; v1(4535,2225) 4551.23,2208.76 J27.2@4551.23,2168.04
  BOTTOM w10: C155.1@4255.32,1720 R201.1@4255.32,1760 4298,1802.68 4298,2170 ; R205.1@4390,2345.32 4390,2220 4395,2215
  BOTTOM w15: v1(3637.85,2225) 3640,2222.85 C168.1@3640,2189.68 ; v1(3845,2435) 3870,2410 C167.1@3870,2384.68 ; v1(4078.79,2110) 4080,2111.21 C169.1@4080,2150.32 ; C161.1@4375.32,2180 4375.32,2195.32 4395,2215 4509.68,2215 C170.1@4535,2189.68 v1(4535,2225)
  other v1: 4038.79,2110
MINIPCIE_NWDISABLE: J7.61 R208.2 | length 1977.4
  TOP w6.16: v1(2505.12,2011.61) 2524.8,2031.3 J7.61@2524.8,2110.98
  ART03 w5.61: v1(2505.12,2011.61) 2541.73,1975 2595,1975 2685.88,1884.12 3059.12,1884.12 3080,1905 3220,1905 3240,1885 3316.8,1885 3370,1938.19 3548.2,1938.19 3565,1955 3760,1955 3785,1980 4050,1980 4160,2090 v1(4160,2110)
  BOTTOM w6.16: v1(4160,2110) R208.2@4160,2150.32
MIPI0_PWR_EN: J6.74 R171.1 | length 2920
  TOP w6.16: J6.74@2642.91,654.29 2642.91,772.91 3125,1255 v1(3175,1255) ; v1(4735,1530) 4755.92,1550.92 4755.92,1911.24 R171.1@4760,1915.32
  ART03 w5.61: v1(3175,1255) 3210,1290 4339.75,1290 4559.75,1510 4630,1510 4650,1530 v1(4735,1530)
MIPI1_PWR_EN: J5.16 R170.1 | length 4527
  TOP w6.16: v1(949.36,1775) 995,1775 1087.79,1867.79 J5.16@1087.79,1953.5 ; v1(4450,1170) 4647,1170 4716.68,1100.32 R170.1@4760,1100.32
  ART03 w5.61: v1(949.36,1775) 949.36,1535.64 1065,1420 2005,1420 2215,1210 4370,1210 4390,1230 4420,1230 4450,1200 v1(4450,1170)
MIPI_CSI_RX_CLK0N: J5.78 J23.10 | length 4279
  TOP w4.88: J5.78@1698.02,1953.5 1698.02,1990.43 1695.08,1993.38 1695.08,2006.47 v1(1701.18,2012.57)
  ART03 w4.44: v1(1701.18,2012.57) 1694.4,2005.79 1694.4,1989.44 1698.84,1985 1724.56,1985 1752,2012.44 1802.56,2012.44 1830,1985 1840,1985 1861.76,2006.76 1861.76,2013.04 1840.69,2034.1 1840.69,2050.69 1854.26,2064.26 1870.84,2064.26 1891.91,2043.19 1898.19,2043.19 1975,2120 2675,2120 2727.44,2172.44 3082.56,2172.44 3110,2145 3340,2145 3370,2175 3455,2175 3487.5,2207.5 3657.5,2207.5 3705,2255 4912.94,2255 4980,2322.06 4980,2365 5020,2405 5050,2405 5086.56,2441.56 ccw(c5081.56,2446.56) 5086.56,2451.56 cw(c5089.7,2454.7) 5086.56,2457.84 5092.84,2464.12 cw(c5095.98,2460.98) 5099.12,2464.12 ccw(c5104.12,2469.12) 5109.12,2464.12 5111.68,2466.68 ccw(c5106.68,2471.68) 5111.68,2476.68 cw(c5116.68,2481.68) 5111.68,2486.68 5114.24,2489.24 cw(c5119.24,2484.24) 5124.24,2489.24 ccw(c5129.24,2494.24) 5134.24,2489.24 5167.17,2522.17 5205.15,2522.17 5212.32,2515 5257.41,2515 5264.57,2522.17 5298.22,2522.17 v1(5305,2528.95)
  BOTTOM w4.88: J23.10@5135.46,2525.79 5168.54,2525.79 5171.94,2522.39 5298.44,2522.39 v1(5305,2528.95)
MIPI_CSI_RX_CLK0P: J5.76 J23.9 | length 4271.1
  TOP w4.88: v1(1675.18,2012.57) 1682.2,2005.54 1682.2,1993.74 1678.34,1989.88 J5.76@1678.34,1953.5
  ART03 w4.44: v1(1675.18,2012.57) 1681.96,2005.79 1681.96,1984.29 1693.69,1972.56 1729.71,1972.56 1757.15,2000 1797.41,2000 1824.85,1972.56 1845.15,1972.56 1874.19,2001.6 1874.19,2018.19 1853.13,2039.26 1853.13,2045.53 1859.41,2051.82 1865.69,2051.82 1886.76,2030.75 1903.34,2030.75 1980.15,2107.56 2680.15,2107.56 2732.59,2160 3077.41,2160 3104.85,2132.56 3345.15,2132.56 3375.15,2162.56 3460.15,2162.56 3492.65,2195.06 3662.65,2195.06 3710.15,2242.56 4918.09,2242.56 4992.44,2316.91 4992.44,2359.85 5025.15,2392.56 5055.15,2392.56 5172.32,2509.73 5200,2509.73 5207.17,2502.56 5262.56,2502.56 5269.73,2509.73 5298.22,2509.73 v1(5305,2502.95)
  BOTTOM w4.88: J23.9@5135.46,2506.1 5168.54,2506.1 5171.94,2509.51 5298.44,2509.51 v1(5305,2502.95)
MIPI_CSI_RX_CLK1N: J5.77 J24.10 | length 5257.3
  TOP w4.88: J5.77@1698.02,2110.98 1698.02,2064.88 1707.9,2055 1730.46,2055 1750,2035.46 1750,1775 v1(1760,1765)
  ART03 w4.44: v1(1760,1765) 1752.44,1757.44 1752.44,1747.36 1759.8,1740 1791.95,1740 1796.39,1744.44 1796.39,1763.27 1808.12,1775 1827.3,1775 1839.03,1763.27 1839.03,1751.88 1843.47,1747.44 1852.35,1747.44 1856.79,1751.88 1856.79,1763.27 1868.52,1775 1887.7,1775 1899.43,1763.27 1899.43,1744.44 1903.87,1740 1926.49,1740 ccw(c1926.49,1745) 1931.49,1745 cw(c1936.49,1745) 1936.49,1750 1944.25,1750 cw(c1944.25,1745) 1949.25,1745 ccw(c1954.25,1745) 1954.25,1740 1962.01,1740 ccw(c1962.01,1745) 1967.01,1745 cw(c1972.01,1745) 1972.01,1750 1979.77,1750 cw(c1979.77,1745) 1984.77,1745 ccw(c1989.77,1745) 1989.77,1740 2115,1740 2136.25,1718.75 2142.53,1718.75 2182.94,1759.16 2199.53,1759.16 2213.1,1745.6 2213.1,1729.01 2172.68,1688.6 2172.68,1682.32 2178.96,1676.04 2185.24,1676.04 2228.81,1719.61 2245.39,1719.61 2258.96,1706.04 2258.96,1689.45 2215.4,1645.88 2215.4,1639.6 2245,1610 2272.41,1610 2283.48,1621.07 2283.48,1688.27 2295.21,1700 2314.39,1700 2326.12,1688.27 2326.12,1629.44 2330.56,1625 2550,1625 2600,1675 2843.1,1675 2854.83,1663.27 2854.83,1616.88 2859.27,1612.44 2868.15,1612.44 2872.59,1616.88 2872.59,1663.27 2884.31,1675 2904.06,1675 2915.79,1663.27 2915.79,1606.88 2920.23,1602.44 2929.11,1602.44 2933.55,1606.88 2933.55,1663.27 2945.27,1675 2964.46,1675 2976.19,1663.27 2976.19,1606.88 2980.63,1602.44 2989.51,1602.44 2993.95,1606.88 2993.95,1663.27 3005.67,1675 3030,1675 3100,1605 4052.41,1605 4079.85,1632.44 4214.85,1632.44 4432.41,1850 4626.45,1850 4630.89,1854.44 4630.89,1878.27 4642.61,1890 4661.8,1890 4673.53,1878.27 4673.53,1854.44 4677.97,1850 4687.41,1850 4692.57,1855.17 4692.57,1903.27 4704.3,1915 4723.49,1915 4735.21,1903.27 4735.21,1854.44 4739.65,1850 4748.53,1850 4752.97,1854.44 4752.97,1903.27 4764.7,1915 4783.89,1915 4795.61,1903.27 4795.61,1854.44 4800.05,1850 4811.5,1850 4815.94,1854.44 4815.94,1903.27 4827.67,1915 4846.85,1915 4858.58,1903.27 4858.58,1869.44 4863.02,1865 4881.05,1865 v1(4885.53,1869.47)
  BOTTOM w4.88: v1(4885.53,1869.47) 4893.15,1861.85 5098.45,1861.85 5102.38,1865.79 J24.10@5135.46,1865.79
MIPI_CSI_RX_CLK1P: J5.75 J24.9 | length 5258.3
  TOP w4.88: J5.75@1678.34,2110.98 1678.34,2066.35 1702.57,2042.12 1725.12,2042.12 1737.12,2030.12 1737.12,1772.12 v1(1730,1765)
  ART03 w4.44: v1(1730,1765) 1740,1755 1740,1742.21 1754.65,1727.56 1797.1,1727.56 1808.83,1739.29 1808.83,1758.12 1813.27,1762.56 1822.15,1762.56 1826.59,1758.12 1826.59,1746.73 1838.32,1735 1857.5,1735 1869.23,1746.73 1869.23,1758.12 1873.67,1762.56 1882.55,1762.56 1886.99,1758.12 1886.99,1739.29 1898.72,1727.56 2109.85,1727.56 2131.1,1706.31 2147.68,1706.31 2188.09,1746.72 2194.37,1746.72 2200.66,1740.44 2200.66,1734.16 2160.24,1693.75 2160.24,1677.16 2173.81,1663.6 2190.39,1663.6 2233.96,1707.17 2240.24,1707.17 2246.52,1700.88 2246.52,1694.6 2202.96,1651.04 2202.96,1634.45 2239.85,1597.56 2277.56,1597.56 2295.92,1615.92 2295.92,1683.12 2300.36,1687.56 2309.24,1687.56 2313.68,1683.12 2313.68,1624.29 2325.41,1612.56 2555.15,1612.56 2605.16,1662.56 2837.95,1662.56 2842.39,1658.12 2842.39,1611.73 2854.11,1600 2873.3,1600 2885.03,1611.73 2885.03,1658.12 2889.47,1662.56 2898.91,1662.56 2903.35,1658.12 2903.35,1601.73 2915.07,1590 2934.26,1590 2945.99,1601.73 2945.99,1658.12 2950.43,1662.56 2959.31,1662.56 2963.75,1658.12 2963.75,1601.73 2975.47,1590 2994.66,1590 3006.39,1601.73 3006.39,1658.12 3010.83,1662.56 3024.85,1662.56 3094.85,1592.56 4057.56,1592.56 4085,1620 4220,1620 4437.56,1837.56 4631.6,1837.56 4643.33,1849.29 4643.33,1873.12 4647.77,1877.56 4656.65,1877.56 4661.09,1873.12 4661.09,1849.29 4672.81,1837.56 4692.56,1837.56 4705.01,1850.02 4705.01,1898.12 4709.45,1902.56 4718.33,1902.56 4722.77,1898.12 4722.77,1849.29 4734.5,1837.56 4753.69,1837.56 4765.41,1849.29 4765.41,1898.12 4769.85,1902.56 4778.73,1902.56 4783.17,1898.12 4783.17,1849.29 4794.9,1837.56 4816.65,1837.56 4828.38,1849.29 4828.38,1898.12 4832.82,1902.56 4841.7,1902.56 4846.14,1898.12 4846.14,1864.29 4857.87,1852.56 4876.44,1852.56 v1(4885.53,1843.47)
  BOTTOM w4.88: v1(4885.53,1843.47) 4891.03,1848.97 5099.51,1848.97 5102.38,1846.1 J24.9@5135.46,1846.1
MIPI_CSI_RX_D0N: J5.70 J23.12 | length 4268.4
  TOP w4.88: J5.70@1619.28,1953.5 1619.28,1990.43 1616.34,1993.38 1616.34,2006.47 v1(1622.44,2012.57)
  ART03 w4.44: v1(1622.44,2012.57) 1611.94,2023.07 1611.94,2044.35 1630.15,2062.56 1674.85,2062.56 1694.85,2042.56 1780.15,2042.56 1795.59,2058 cw(c1799.95,2053.65) 1804.3,2058 ccw(c1807.44,2061.14) 1810.58,2058 1816.86,2064.28 ccw(c1813.72,2067.42) 1816.86,2070.56 cw(c1821.21,2074.91) 1816.86,2079.27 1820.71,2083.12 cw(c1825.06,2078.77) 1829.42,2083.12 ccw(c1832.56,2086.26) 1835.7,2083.12 1841.97,2089.4 ccw(c1838.84,2092.54) 1841.98,2095.68 ; 1841.97,2095.68 cw(c1846.33,2100.03) 1841.97,2104.38 ; 1841.97,2104.38 1845.83,2108.24 cw(c1850.18,2103.89) 1854.53,2108.24 ccw(c1857.67,2111.38) 1860.81,2108.24 1867.09,2114.52 ccw(c1863.95,2117.66) 1867.09,2120.8 cw(c1871.44,2125.15) 1867.09,2129.5 1875.15,2137.56 2665.15,2137.56 2717.59,2190 3100,2190 3107.44,2182.56 3126.07,2182.56 cw(c3126.07,2178.78) 3129.85,2178.78 ccw(c3133.63,2178.78) 3133.63,2175 3143.83,2175 ccw(c3143.83,2178.78) 3147.61,2178.78 cw(c3151.39,2178.78) 3151.39,2182.56 3318.7,2182.56 3333.7,2197.56 3440.15,2197.56 3490.15,2247.56 3650.15,2247.56 3677.9,2275.3 4282.38,2275.3 4294.11,2287.03 4294.11,2293.12 4298.55,2297.56 4307.43,2297.56 4311.87,2293.12 4311.87,2287.03 4323.59,2275.3 4342.78,2275.3 4354.51,2287.03 4354.51,2293.12 4358.95,2297.56 4367.83,2297.56 4372.27,2293.12 4372.27,2287.03 4383.99,2275.3 4418.42,2275.3 4435.68,2292.56 4460.73,2292.56 4477.98,2275.3 4847.9,2275.3 5165.15,2592.56 5187.02,2592.56 cw(c5187.02,2586.28) 5193.3,2586.28 ccw(c5199.58,2586.28) 5199.58,2580 5204.78,2580 ccw(c5204.78,2586.28) 5211.06,2586.28 cw(c5217.34,2586.28) 5217.34,2592.56 5249.85,2592.56 5255,2587.41 5255,2565.98 5250.56,2561.54 5242.39,2561.54 v1(5235.61,2568.32)
  BOTTOM w4.88: J23.12@5135.46,2565.16 5168.54,2565.16 5171.94,2561.76 5229.05,2561.76 v1(5235.61,2568.32)
MIPI_CSI_RX_D0P: J5.68 J23.11 | length 4268.6
  TOP w4.88: v1(1596.44,2012.57) 1603.46,2005.54 1603.46,1993.74 1599.6,1989.88 J5.68@1599.6,1953.5
  ART03 w4.44: v1(1596.44,2012.57) 1599.5,2015.62 1599.5,2049.5 1625,2075 1680,2075 1700,2055 1775,2055 1870,2150 2660,2150 2712.44,2202.44 3105.15,2202.44 3112.59,2195 3313.55,2195 3328.55,2210 3435,2210 3485,2260 3645,2260 3672.74,2287.74 4277.23,2287.74 4281.67,2292.18 4281.67,2298.27 4293.39,2310 4312.58,2310 4324.31,2298.27 4324.31,2292.18 4328.75,2287.74 4337.63,2287.74 4342.07,2292.18 4342.07,2298.27 4353.79,2310 4372.98,2310 4384.71,2298.27 4384.71,2292.18 4389.15,2287.74 4413.27,2287.74 4430.53,2305 4465.88,2305 4483.14,2287.74 4842.74,2287.74 5160,2605 5255,2605 5267.44,2592.56 5267.44,2560.82 5255.71,2549.1 5242.39,2549.1 v1(5235.61,2542.32)
  BOTTOM w4.88: J23.11@5135.46,2545.47 5168.54,2545.47 5171.94,2548.88 5229.05,2548.88 v1(5235.61,2542.32)
MIPI_CSI_RX_D1N: J5.74 J23.8 | length 4275.3
  TOP w4.88: J5.74@1658.65,1953.5 1658.65,1917.12 1654.79,1913.26 1654.79,1901.46 v1(1661.81,1894.43)
  ART03 w4.44: v1(1661.81,1894.43) 1655.68,1900.56 1655.68,1923.09 1665.15,1932.56 1860.15,1932.56 2002.59,2075 2692.59,2075 2747.59,2130 3057.41,2130 3114.85,2072.56 3160.15,2072.56 3185.15,2097.56 3230.38,2097.56 3247.61,2080.32 3277.92,2080.32 3302.05,2104.46 3384.46,2104.46 3407.56,2127.56 3499.89,2127.56 3511.62,2139.29 3511.62,2153.12 3516.06,2157.56 3524.94,2157.56 3529.38,2153.12 3529.38,2139.29 3541.11,2127.56 3560.29,2127.56 3572.02,2139.29 3572.02,2153.12 3576.46,2157.56 3585.34,2157.56 3589.78,2153.12 3589.78,2139.29 3601.51,2127.56 3660.15,2127.56 3725.15,2192.56 4570.15,2192.56 4592.05,2214.46 4957.05,2214.46 5175.15,2432.56 5219.85,2432.56 5227.41,2425 5263.75,2425 5280,2441.25 5280,2455 v1(5290,2465)
  BOTTOM w4.88: J23.8@5135.46,2486.42 5268.58,2486.42 v1(5290,2465)
MIPI_CSI_RX_D1P: J5.72 J23.7 | length 4266.5
  TOP w4.88: v1(1635.81,1894.43) 1641.91,1900.53 1641.91,1913.62 1638.97,1916.57 J5.72@1638.97,1953.5
  ART03 w4.44: v1(1635.81,1894.43) 1643.24,1901.87 1643.24,1928.24 1660,1945 1738.02,1945 ccw(c1738.02,1950) 1743.02,1950 cw(c1748.02,1950) 1748.02,1955 1755.78,1955 cw(c1755.78,1950) 1760.78,1950 ccw(c1765.78,1950) 1765.78,1945 1773.54,1945 ccw(c1773.54,1950) 1778.54,1950 cw(c1783.54,1950) 1783.54,1955 1791.3,1955 cw(c1791.3,1950) 1796.3,1950 ccw(c1801.3,1950) 1801.3,1945 1855,1945 1997.44,2087.44 2687.44,2087.44 2742.44,2142.44 3062.56,2142.44 3120,2085 3155,2085 3180,2110 3235.53,2110 3252.77,2092.76 3272.76,2092.76 3296.9,2116.9 3379.31,2116.9 3402.41,2140 3494.74,2140 3499.18,2144.44 3499.18,2158.27 3510.91,2170 3530.09,2170 3541.82,2158.27 3541.82,2144.44 3546.26,2140 3555.14,2140 3559.58,2144.44 3559.58,2158.27 3571.31,2170 3590.49,2170 3602.22,2158.27 3602.22,2144.44 3606.66,2140 3655,2140 3720,2205 4565,2205 4586.9,2226.9 4951.9,2226.9 5170,2445 5225,2445 5232.56,2437.44 5258.59,2437.44 5267.56,2446.41 5267.56,2457.44 v1(5260,2465)
  BOTTOM w4.88: J23.7@5135.46,2466.73 5171.73,2466.73 5178.54,2473.54 5255.12,2473.54 5260,2468.66 v1(5260,2465)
